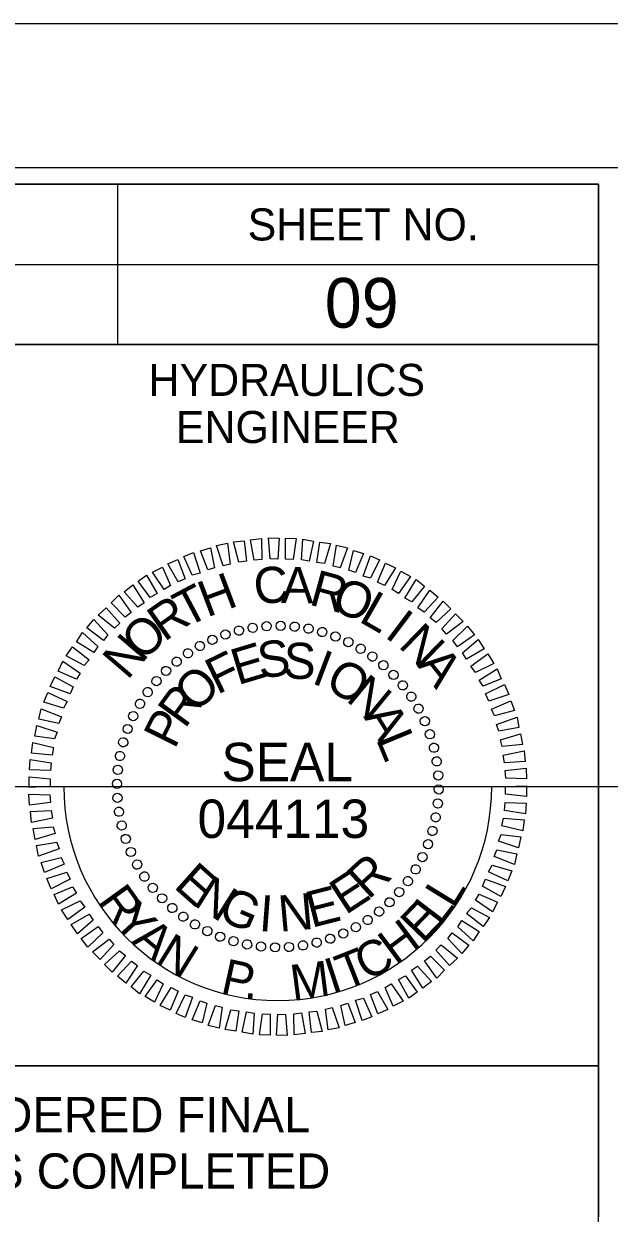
# Model space of a CAD drawing. Extents: x 1263639 to 1265460, y 747271 to 748371.
# Drawn here: x 1265216.1 to 1265307.4, y 748185.2 to 748370.7 of the extents above; entities that cross this region are included whole.
import ezdxf

# ---------------------------------------------------------------- set-up
doc = ezdxf.new("R2010")
doc.units = 0
for name, color, linetype in [('Prop Drainage Structure Bridge', 7, 'Continuous'), ('Prop Drainage Structure Bridge Opening', 7, 'Continuous'), ('Prop Grid Mask', 7, 'Continuous'), ('Prop Horizontal Alignment', 7, 'Continuous'), ('Prop Paved Shoulder', 7, 'Continuous'), ('Prop Terminator CELL', 7, 'Continuous'), ('Prop VPI Label', 7, 'Continuous'), ('Sheet Border Standard 30in CELL', 7, 'Continuous'), ('Sheet Layout Plan Border', 7, 'Continuous')]:
    doc.layers.add(name, color=color, linetype=linetype)

msp = doc.modelspace()

# ---------------------------------------------------------------- linework, layer by layer
at = {"layer": 'Prop Drainage Structure Bridge'}
for p, q in [((1265251.85, 748276.5), (1265251.85, 748276.5)), ((1265254, 748276.8), (1265254, 748276.8)), ((1265256.2, 748276.85), (1265256.2, 748276.85)), ((1265258.4, 748276.7), (1265258.4, 748276.7)), ((1265260.55, 748276.35), (1265260.55, 748276.35)), ((1265245.55, 748274.7), (1265245.55, 748274.7)), ((1265247.55, 748275.5), (1265247.55, 748275.5)), ((1265249.65, 748276.1), (1265249.65, 748276.1)), ((1265262.65, 748275.9), (1265262.65, 748275.9)), ((1265264.75, 748275.2), (1265264.75, 748275.2)), ((1265266.75, 748274.3), (1265266.75, 748274.3)), ((1265241.7, 748272.55), (1265241.7, 748272.55)), ((1265243.6, 748273.7), (1265243.6, 748273.7)), ((1265268.7, 748273.3), (1265268.7, 748273.3)), ((1265239.95, 748271.3), (1265239.95, 748271.3)), ((1265270.5, 748272.05), (1265270.5, 748272.05)), ((1265272.25, 748270.7), (1265272.25, 748270.7)), ((1265238.3, 748269.8), (1265238.3, 748269.8)), ((1265273.8, 748269.2), (1265273.8, 748269.2)), ((1265236.8, 748268.25), (1265236.8, 748268.25)), ((1265275.3, 748267.55), (1265275.3, 748267.55)), ((1265235.45, 748266.5), (1265235.45, 748266.5)), ((1265276.55, 748265.8), (1265276.55, 748265.8)), ((1265234.2, 748264.7), (1265234.2, 748264.7)), ((1265277.7, 748263.9), (1265277.7, 748263.9)), ((1265233.2, 748262.75), (1265233.2, 748262.75)), ((1265278.7, 748261.95), (1265278.7, 748261.95)), ((1265232.3, 748260.75), (1265232.3, 748260.75)), ((1265279.5, 748259.95), (1265279.5, 748259.95)), ((1265231.6, 748258.65), (1265231.6, 748258.65)), ((1265280.1, 748257.85), (1265280.1, 748257.85)), ((1265231.15, 748256.55), (1265231.15, 748256.55)), ((1265230.8, 748254.4), (1265230.8, 748254.4)), ((1265280.5, 748255.65), (1265280.5, 748255.65)), ((1265230.65, 748252.2), (1265230.65, 748252.2)), ((1265280.8, 748253.5), (1265280.8, 748253.5)), ((1265255.75, 748251.75), (1265255.75, 748251.75)), ((1265280.85, 748251.3), (1265280.85, 748251.3)), ((1265230.7, 748250), (1265230.7, 748250)), ((1265280.7, 748249.1), (1265280.7, 748249.1)), ((1265231, 748247.85), (1265231, 748247.85)), ((1265280.35, 748246.95), (1265280.35, 748246.95)), ((1265231.4, 748245.65), (1265231.4, 748245.65)), ((1265279.9, 748244.85), (1265279.9, 748244.85)), ((1265232, 748243.55), (1265232, 748243.55)), ((1265279.2, 748242.75), (1265279.2, 748242.75)), ((1265232.8, 748241.55), (1265232.8, 748241.55)), ((1265233.8, 748239.6), (1265233.8, 748239.6)), ((1265278.3, 748240.75), (1265278.3, 748240.75)), ((1265234.95, 748237.7), (1265234.95, 748237.7)), ((1265277.3, 748238.8), (1265277.3, 748238.8)), ((1265236.2, 748235.95), (1265236.2, 748235.95)), ((1265276.05, 748237), (1265276.05, 748237)), ((1265237.7, 748234.3), (1265237.7, 748234.3)), ((1265273.2, 748233.7), (1265273.2, 748233.7)), ((1265274.7, 748235.25), (1265274.7, 748235.25)), ((1265239.25, 748232.8), (1265239.25, 748232.8)), ((1265271.55, 748232.2), (1265271.55, 748232.2)), ((1265241, 748231.45), (1265241, 748231.45)), ((1265242.8, 748230.2), (1265242.8, 748230.2)), ((1265267.9, 748229.8), (1265267.9, 748229.8)), ((1265269.8, 748230.95), (1265269.8, 748230.95)), ((1265244.75, 748229.2), (1265244.75, 748229.2)), ((1265246.75, 748228.3), (1265246.75, 748228.3)), ((1265263.95, 748228), (1265263.95, 748228)), ((1265265.95, 748228.8), (1265265.95, 748228.8)), ((1265248.85, 748227.6), (1265248.85, 748227.6)), ((1265250.95, 748227.15), (1265250.95, 748227.15)), ((1265253.1, 748226.8), (1265253.1, 748226.8)), ((1265255.3, 748226.65), (1265255.3, 748226.65)), ((1265257.5, 748226.7), (1265257.5, 748226.7)), ((1265259.65, 748227), (1265259.65, 748227)), ((1265261.85, 748227.4), (1265261.85, 748227.4))]:
    msp.add_line(p, q, dxfattribs=at)
for points in [[(1265247.25, 748286.2), (1265246.2, 748289.35), (1265247.9, 748289.7), (1265248.3, 748286.45)], [(1265249.65, 748286.75), (1265248.85, 748289.95), (1265250.5, 748290.1), (1265250.85, 748286.9)], [(1265252.05, 748287.05), (1265251.5, 748290.25), (1265253.2, 748290.45), (1265253.25, 748287.2)], [(1265254.55, 748287.3), (1265254.3, 748290.55), (1265255.95, 748290.5), (1265255.75, 748287.25)], [(1265256.95, 748287.25), (1265256.95, 748290.5), (1265258.6, 748290.45), (1265258.15, 748287.2)], [(1265259.45, 748287.1), (1265259.65, 748290.35), (1265261.3, 748290.05), (1265260.65, 748286.9)], [(1265261.85, 748286.7), (1265262.3, 748289.9), (1265263.95, 748289.65), (1265263.05, 748286.55)], [(1265264.4, 748286.15), (1265264.9, 748289.4), (1265266.6, 748289), (1265265.45, 748285.9)], [(1265242.4, 748284.75), (1265241.1, 748287.65), (1265242.6, 748288.25), (1265243.65, 748285.05)], [(1265244.85, 748285.55), (1265243.7, 748288.55), (1265245.25, 748289), (1265245.9, 748285.9)], [(1265266.8, 748285.5), (1265267.55, 748288.6), (1265269.1, 748288.1), (1265267.85, 748285.15)], [(1265269.05, 748284.6), (1265270.2, 748287.75), (1265271.6, 748287.15), (1265270.2, 748284.25)], [(1265238.05, 748282.5), (1265236.2, 748285.2), (1265237.75, 748286), (1265239, 748283.1)], [(1265240.2, 748283.7), (1265238.6, 748286.5), (1265240.15, 748287.2), (1265241.3, 748284.15)], [(1265271.3, 748283.65), (1265272.55, 748286.6), (1265274.1, 748285.9), (1265272.4, 748283.1)], [(1265235.85, 748281.25), (1265234, 748283.8), (1265235.3, 748284.75), (1265236.95, 748281.85)], [(1265273.6, 748282.5), (1265274.95, 748285.35), (1265276.45, 748284.5), (1265274.55, 748281.9)], [(1265275.55, 748281.15), (1265277.3, 748284.05), (1265278.6, 748283), (1265276.65, 748280.55)], [(1265233.95, 748279.75), (1265231.8, 748282.15), (1265233.15, 748283.2), (1265234.9, 748280.4)], [(1265277.6, 748279.65), (1265279.45, 748282.4), (1265280.75, 748281.3), (1265278.55, 748278.95)], [(1265231.95, 748278.2), (1265229.75, 748280.4), (1265230.95, 748281.6), (1265232.9, 748278.9)], [(1265279.5, 748278.1), (1265281.55, 748280.7), (1265282.75, 748279.5), (1265280.45, 748277.35)], [(1265230.3, 748276.45), (1265227.75, 748278.5), (1265229, 748279.65), (1265231.1, 748277.25)], [(1265281.3, 748276.35), (1265283.45, 748278.7), (1265284.65, 748277.5), (1265282.05, 748275.55)], [(1265228.55, 748274.55), (1265225.95, 748276.5), (1265227.05, 748277.8), (1265229.25, 748275.45)], [(1265283.05, 748274.55), (1265285.35, 748276.8), (1265286.4, 748275.45), (1265283.75, 748273.55)], [(1265227.05, 748272.65), (1265224.35, 748274.35), (1265225.3, 748275.8), (1265227.7, 748273.6)], [(1265284.55, 748272.6), (1265287, 748274.7), (1265287.95, 748273.25), (1265285.15, 748271.65)], [(1265225.55, 748270.65), (1265222.75, 748272.15), (1265223.75, 748273.55), (1265226.35, 748271.55)], [(1265285.85, 748270.55), (1265288.5, 748272.45), (1265289.45, 748270.95), (1265286.55, 748269.55)], [(1265224.35, 748268.5), (1265221.5, 748269.75), (1265222.25, 748271.3), (1265224.95, 748269.45)], [(1265223.35, 748266.2), (1265220.25, 748267.35), (1265221, 748268.9), (1265223.85, 748267.3)], [(1265287.15, 748268.35), (1265289.95, 748270.1), (1265290.6, 748268.55), (1265287.75, 748267.4)], [(1265288.15, 748266.2), (1265291.1, 748267.7), (1265291.75, 748266.1), (1265288.65, 748265.1)], [(1265222.35, 748264), (1265219.25, 748264.9), (1265219.9, 748266.45), (1265222.9, 748265.05)], [(1265289.05, 748263.85), (1265292.1, 748265.15), (1265292.65, 748263.6), (1265289.55, 748262.8)], [(1265221.6, 748261.6), (1265218.5, 748262.25), (1265218.85, 748263.9), (1265222, 748262.65)], [(1265220.95, 748259.2), (1265217.85, 748259.6), (1265218.2, 748261.3), (1265221.35, 748260.25)], [(1265289.85, 748261.45), (1265293.05, 748262.6), (1265293.35, 748260.95), (1265290.2, 748260.4)], [(1265290.45, 748259.05), (1265293.6, 748260), (1265293.9, 748258.3), (1265290.75, 748258)], [(1265220.55, 748256.65), (1265217.35, 748256.95), (1265217.55, 748258.65), (1265220.8, 748257.85)], [(1265220.3, 748254.25), (1265217.05, 748254.35), (1265217.15, 748256), (1265220.4, 748255.45)], [(1265290.9, 748256.65), (1265294.15, 748257.35), (1265294.3, 748255.65), (1265291.1, 748255.45)], [(1265291.2, 748254.25), (1265294.45, 748254.65), (1265294.55, 748252.95), (1265291.3, 748253.05)], [(1265220.25, 748251.75), (1265217, 748251.6), (1265217, 748253.3), (1265220.25, 748252.95)], [(1265220.3, 748249.25), (1265217.05, 748248.85), (1265216.95, 748250.55), (1265220.2, 748250.45)], [(1265291.25, 748251.75), (1265294.5, 748251.9), (1265294.5, 748250.2), (1265291.25, 748250.55)], [(1265291.2, 748249.25), (1265294.45, 748249.15), (1265294.35, 748247.5), (1265291.1, 748248.05)], [(1265220.6, 748246.85), (1265217.35, 748246.15), (1265217.2, 748247.85), (1265220.4, 748248.05)], [(1265290.95, 748246.85), (1265294.15, 748246.55), (1265293.95, 748244.85), (1265290.7, 748245.65)], [(1265221.05, 748244.45), (1265217.9, 748243.5), (1265217.6, 748245.2), (1265220.75, 748245.5)], [(1265221.65, 748242.05), (1265218.45, 748240.9), (1265218.15, 748242.55), (1265221.3, 748243.1)], [(1265290.55, 748244.3), (1265293.65, 748243.9), (1265293.3, 748242.2), (1265290.15, 748243.25)], [(1265289.9, 748241.9), (1265293, 748241.25), (1265292.65, 748239.6), (1265289.5, 748240.85)], [(1265222.45, 748239.65), (1265219.4, 748238.35), (1265218.85, 748239.9), (1265221.95, 748240.7)], [(1265289.15, 748239.5), (1265292.25, 748238.6), (1265291.6, 748237.05), (1265288.6, 748238.45)], [(1265223.35, 748237.3), (1265220.4, 748235.8), (1265219.75, 748237.4), (1265222.85, 748238.4)], [(1265288.15, 748237.3), (1265291.25, 748236.15), (1265290.5, 748234.6), (1265287.65, 748236.2)], [(1265224.35, 748235.15), (1265221.55, 748233.4), (1265220.9, 748234.95), (1265223.75, 748236.1)], [(1265225.65, 748232.95), (1265223, 748231.05), (1265222.05, 748232.55), (1265224.95, 748233.95)], [(1265287.15, 748235), (1265290, 748233.75), (1265289.25, 748232.2), (1265286.55, 748234.05)], [(1265226.95, 748230.9), (1265224.5, 748228.8), (1265223.55, 748230.25), (1265226.35, 748231.85)], [(1265285.95, 748232.85), (1265288.75, 748231.35), (1265287.75, 748229.95), (1265285.15, 748231.95)], [(1265228.45, 748228.95), (1265226.15, 748226.7), (1265225.1, 748228.05), (1265227.75, 748229.95)], [(1265284.45, 748230.85), (1265287.15, 748229.15), (1265286.2, 748227.7), (1265283.8, 748229.9)], [(1265230.2, 748227.15), (1265228.05, 748224.8), (1265226.85, 748226), (1265229.45, 748227.95)], [(1265282.95, 748228.95), (1265285.55, 748227), (1265284.45, 748225.7), (1265282.25, 748228.05)], [(1265232, 748225.4), (1265229.95, 748222.8), (1265228.75, 748224), (1265231.05, 748226.15)], [(1265281.2, 748227.05), (1265283.75, 748225), (1265282.5, 748223.85), (1265280.4, 748226.25)], [(1265233.9, 748223.85), (1265232.05, 748221.1), (1265230.75, 748222.2), (1265232.95, 748224.55)], [(1265279.55, 748225.3), (1265281.75, 748223.1), (1265280.55, 748221.9), (1265278.6, 748224.6)], [(1265235.95, 748222.35), (1265234.2, 748219.45), (1265232.9, 748220.5), (1265234.85, 748222.95)], [(1265277.55, 748223.75), (1265279.7, 748221.35), (1265278.35, 748220.3), (1265276.6, 748223.1)], [(1265237.9, 748221), (1265236.55, 748218.15), (1265235.05, 748219), (1265236.95, 748221.6)], [(1265273.45, 748221), (1265275.3, 748218.3), (1265273.75, 748217.5), (1265272.5, 748220.4)], [(1265275.65, 748222.25), (1265277.5, 748219.7), (1265276.2, 748218.75), (1265274.55, 748221.65)], [(1265240.2, 748219.85), (1265238.95, 748216.9), (1265237.4, 748217.6), (1265239.1, 748220.4)], [(1265242.45, 748218.9), (1265241.3, 748215.75), (1265239.9, 748216.35), (1265241.3, 748219.25)], [(1265269.1, 748218.75), (1265270.4, 748215.85), (1265268.9, 748215.25), (1265267.85, 748218.45)], [(1265271.3, 748219.8), (1265272.9, 748217), (1265271.35, 748216.3), (1265270.2, 748219.35)], [(1265244.7, 748218), (1265243.95, 748214.9), (1265242.4, 748215.4), (1265243.65, 748218.35)], [(1265247.1, 748217.35), (1265246.6, 748214.1), (1265244.9, 748214.5), (1265246.05, 748217.6)], [(1265249.65, 748216.8), (1265249.2, 748213.6), (1265247.55, 748213.85), (1265248.45, 748216.95)], [(1265264.25, 748217.3), (1265265.3, 748214.15), (1265263.6, 748213.8), (1265263.2, 748217.05)], [(1265266.65, 748217.95), (1265267.8, 748214.95), (1265266.25, 748214.5), (1265265.6, 748217.6)], [(1265252.05, 748216.4), (1265251.85, 748213.15), (1265250.2, 748213.45), (1265250.85, 748216.6)], [(1265254.55, 748216.25), (1265254.55, 748213), (1265252.9, 748213.05), (1265253.35, 748216.3)], [(1265256.95, 748216.2), (1265257.2, 748212.95), (1265255.55, 748213), (1265255.75, 748216.25)], [(1265259.45, 748216.45), (1265260, 748213.25), (1265258.3, 748213.05), (1265258.25, 748216.3)], [(1265261.85, 748216.75), (1265262.65, 748213.55), (1265261, 748213.4), (1265260.65, 748216.6)]]:
    msp.add_lwpolyline(points, close=True, dxfattribs=at)
for centre, major_axis in [((1265247.59, 748275.47), (-0.234, 0.681)), ((1265249.69, 748276.09), (-0.174, 0.699)), ((1265251.83, 748276.52), (-0.113, 0.711)), ((1265254, 748276.77), (-0.05, 0.718)), ((1265256.19, 748276.83), (0.013, 0.72)), ((1265258.38, 748276.7), (0.075, 0.716)), ((1265260.54, 748276.37), (0.137, 0.707)), ((1265262.67, 748275.86), (0.198, 0.692)), ((1265243.6, 748273.69), (-0.349, 0.63)), ((1265245.55, 748274.66), (-0.293, 0.658)), ((1265264.74, 748275.17), (0.258, 0.672)), ((1265266.75, 748274.29), (0.316, 0.647)), ((1265241.73, 748272.55), (-0.403, 0.597)), ((1265268.67, 748273.25), (0.371, 0.617)), ((1265270.5, 748272.04), (0.423, 0.582)), ((1265238.33, 748269.79), (-0.5, 0.518)), ((1265239.97, 748271.24), (-0.453, 0.56)), ((1265272.21, 748270.68), (0.472, 0.543)), ((1265236.83, 748268.21), (-0.543, 0.472)), ((1265273.8, 748269.17), (0.518, 0.5)), ((1265235.46, 748266.49), (-0.582, 0.423)), ((1265275.24, 748267.54), (0.56, 0.453)), ((1265234.26, 748264.67), (-0.617, 0.371)), ((1265276.55, 748265.78), (0.597, 0.403)), ((1265233.21, 748262.75), (-0.647, 0.316)), ((1265277.69, 748263.91), (0.63, 0.349)), ((1265232.34, 748260.74), (-0.672, 0.258)), ((1265278.67, 748261.95), (0.658, 0.293)), ((1265231.65, 748258.67), (-0.692, 0.198)), ((1265279.47, 748259.92), (0.681, 0.234)), ((1265280.09, 748257.82), (0.699, 0.174)), ((1265231.13, 748256.54), (-0.707, 0.137)), ((1265280.53, 748255.68), (0.711, 0.113)), ((1265230.81, 748254.37), (-0.716, 0.075)), ((1265280.77, 748253.5), (0.718, 0.05)), ((1265230.68, 748252.19), (-0.72, 0.013)), ((1265280.83, 748251.32), (0.72, -0.013)), ((1265230.74, 748250), (-0.718, -0.05)), ((1265230.98, 748247.83), (-0.711, -0.113)), ((1265280.7, 748249.13), (0.716, -0.075)), ((1265231.42, 748245.69), (-0.699, -0.174)), ((1265280.37, 748246.97), (0.707, -0.137)), ((1265279.86, 748244.84), (0.692, -0.198)), ((1265232.04, 748243.59), (-0.681, -0.234)), ((1265279.17, 748242.76), (0.672, -0.258)), ((1265232.84, 748241.55), (-0.658, -0.293)), ((1265278.3, 748240.76), (0.647, -0.316)), ((1265233.82, 748239.59), (-0.63, -0.349)), ((1265277.25, 748238.84), (0.617, -0.371)), ((1265234.96, 748237.73), (-0.597, -0.403)), ((1265276.04, 748237.01), (0.582, -0.423)), ((1265236.26, 748235.97), (-0.56, -0.453)), ((1265274.68, 748235.3), (0.543, -0.472)), ((1265237.71, 748234.33), (-0.518, -0.5)), ((1265239.3, 748232.82), (-0.472, -0.543)), ((1265273.18, 748233.71), (0.5, -0.518)), ((1265241.01, 748231.46), (-0.423, -0.582)), ((1265269.78, 748230.96), (0.403, -0.597)), ((1265271.54, 748232.26), (0.453, -0.56)), ((1265242.84, 748230.26), (-0.371, -0.617)), ((1265244.76, 748229.21), (-0.316, -0.647)), ((1265267.91, 748229.82), (0.349, -0.63)), ((1265246.77, 748228.34), (-0.258, -0.672)), ((1265248.84, 748227.64), (-0.198, -0.692)), ((1265250.97, 748227.13), (-0.137, -0.707)), ((1265261.82, 748227.42), (0.174, -0.699)), ((1265263.92, 748228.04), (0.234, -0.681)), ((1265265.96, 748228.84), (0.293, -0.658)), ((1265253.13, 748226.81), (-0.075, -0.716)), ((1265255.32, 748226.68), (-0.013, -0.72)), ((1265257.5, 748226.73), (0.05, -0.718)), ((1265259.68, 748226.98), (0.113, -0.711))]:
    msp.add_ellipse(centre, major_axis=major_axis, ratio=0.999708, dxfattribs=at)
at = {"layer": 'Prop Drainage Structure Bridge Opening'}
msp.add_line((1265322.75, 748370.74), (1263638.75, 748370.74), dxfattribs=at)
at = {"layer": 'Prop Grid Mask'}
msp.add_line((1265155.7, 748251.75), (1265460.4, 748251.75), dxfattribs=at)
at = {"layer": 'Prop Horizontal Alignment'}
msp.add_arc((1265255.75, 748251.75), 33.36, 180, 360, dxfattribs=at)
at = {"layer": 'Prop Paved Shoulder'}
for p, q in [((1265230.75, 748345.69), (1265230.75, 748320.69)), ((1265105.7, 748333.19), (1265305.75, 748333.19))]:
    msp.add_line(p, q, dxfattribs=at)
for points in [[(1265305.75, 748345.74), (1263805.75, 748345.74), (1263805.75, 747295.74), (1265305.75, 747295.74)], [(1265105.7, 748345.74), (1265305.75, 748345.74), (1265305.75, 748320.69), (1265105.7, 748320.69)], [(1265205.75, 748320.69), (1265305.75, 748320.69), (1265305.75, 748208.19), (1265205.75, 748208.19)]]:
    msp.add_lwpolyline(points, close=True, dxfattribs=at)
at = {"layer": 'Prop Terminator CELL'}
msp.add_lwpolyline([(1265318.25, 748348.29), (1263651.75, 748348.29), (1263651.75, 747293.19), (1265318.25, 747293.19)], close=True, dxfattribs=at)
at = {"layer": 'Prop VPI Label'}
msp.add_lwpolyline([(1265322.75, 748370.74), (1263638.75, 748370.74), (1263638.75, 747270.74), (1265322.75, 747270.74)], close=True, dxfattribs=at)
at = {"layer": 'Sheet Layout Plan Border'}
for p, q in [((1265105.7, 748208.19), (1265305.74, 748208.19)), ((1265305.74, 748208.17), (1265305.74, 748184.67))]:
    msp.add_line(p, q, dxfattribs=at)

# ---------------------------------------------------------------- texts
at = {"layer": 'Prop Drainage Structure Bridge'}
for s, height, rotation, p in [('C', 5.64, 6.2199, (1265252.3, 748280.1)), ('A', 5.64, 359.0203, (1265256.25, 748280.4)), ('R', 5.64, 344.6211, (1265260.45, 748280.2)), ('H', 5.64, 20.6195, (1265244.7, 748278.1)), ('O', 5.64, 337.4212, (1265263.8, 748279.45)), ('T', 5.64, 27.8198, (1265241.45, 748276.45)), ('L', 5.64, 330.2209, (1265268.2, 748277.6)), ('R', 5.64, 35.0205, (1265238.05, 748274.25)), ('O', 5.64, 42.2217, (1265234.6, 748271.15)), ('I', 5.64, 323.0201, (1265272.25, 748275.2)), ('N', 5.64, 315.8189, (1265274.4, 748273.65)), ('N', 5.64, 49.4235, (1265232.3, 748268.25)), ('S', 5.64, 7.2556, (1265252.95, 748268.6)), ('S', 5.64, 357.9004, (1265256.55, 748268.65)), ('F', 5.64, 25.967, (1265246.3, 748266.05)), ('E', 5.64, 16.6111, (1265249.5, 748267.55)), ('I', 5.64, 339.1896, (1265260.85, 748267.95)), ('A', 5.64, 308.6172, (1265277.35, 748270.7)), ('O', 5.64, 329.8335, (1265262.85, 748267.25)), ('O', 5.64, 44.6812, (1265243, 748263.1)), ('N', 5.64, 320.4766, (1265266.2, 748265.25)), ('R', 5.64, 54.0397, (1265241.25, 748260.65)), ('P', 5.64, 63.3989, (1265239.65, 748257.45)), ('A', 5.64, 301.7603, (1265269.05, 748262.65)), ('L', 5.64, 292.4008, (1265271, 748259.2)), ('SEAL', 5.998, 360, (1265246.96, 748252.6)), ('044113', 5.998, 360, (1265243.24, 748243.74)), ('E', 5.64, 318.2769, (1265239.35, 748236.1)), ('R', 5.64, 42.4814, (1265269.85, 748234)), ('N', 5.64, 327.634, (1265242.35, 748233.4)), ('E', 5.64, 33.1241, (1265266.3, 748231.65)), ('R', 5.5, 305.8361, (1265227.53, 748233.85)), ('G', 5.64, 336.9902, (1265246.15, 748231.15)), ('E', 5.64, 14.4118, (1265261, 748229.7)), ('L', 5.5, 58.4194, (1265283.12, 748232.56)), ('Y', 5.5, 312.7625, (1265229.89, 748230.58)), ('I', 5.64, 355.7012, (1265252.7, 748229.25)), ('N', 5.64, 5.0564, (1265256.05, 748229.1)), ('E', 5.5, 46.0262, (1265278.36, 748227.14)), ('L', 5.5, 52.6092, (1265281.04, 748229.89)), ('A', 5.5, 320.0897, (1265232.8, 748227.45)), ('H', 5.5, 36.7814, (1265274.12, 748223.82)), ('N', 5.5, 328.2755, (1265236.49, 748224.43)), ('C', 5.5, 27.9087, (1265269.59, 748221.33)), ('T', 5.5, 21.6119, (1265266.17, 748219.99)), ('P', 5.5, 347.6523, (1265246.65, 748219.59)), ('M', 5.5, 7.4156, (1265258.06, 748218.41)), ('I', 5.5, 18.0915, (1265264.2, 748219.41)), ('.', 5.5, 354.2353, (1265250.4, 748218.76))]:
    msp.add_text(s, height=height, rotation=rotation, dxfattribs=at).set_placement(p)
at = {"layer": 'Prop Paved Shoulder'}
for s, p in [('SHEET NO.', (1265251.05, 748336.94)), ('HYDRAULICS', (1265235.61, 748312.69)), ('ENGINEER', (1265239.86, 748305.34))]:
    msp.add_text(s, height=5, dxfattribs=at).set_placement(p)
at = {"layer": 'Sheet Border Standard 30in CELL'}
msp.add_text('09', height=7.75, dxfattribs=at).set_placement((1265263.07, 748323.34))
at = {"layer": 'Sheet Layout Plan Border'}
for s, p in [('DOCUMENT NOT CONSIDERED FINAL', (1265126.78, 748197.84)), ('UNLESS ALL SIGNATURES COMPLETED', (1265121.7, 748189.04))]:
    msp.add_text(s, height=5.5, dxfattribs=at).set_placement(p)

doc.saveas('drawing.dxf')
